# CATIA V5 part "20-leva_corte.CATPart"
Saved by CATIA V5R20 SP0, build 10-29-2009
Part number: 20-leva_corte
Revision: ANY
Definition: UNKNOWN
Nomenclature: 20-leva_corte
Source: Unknown
Bounding box of the stored display mesh (mm): x -12.5 to 12.5, y -12.31 to 12.31, z -7 to 10.6
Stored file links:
  C:\Users\Utente\Desktop\IO LAVORO\3D X SITO CF\CUMSA\3D files CX.013058\CX 013058\20-leva_corte.CATPart
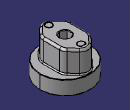
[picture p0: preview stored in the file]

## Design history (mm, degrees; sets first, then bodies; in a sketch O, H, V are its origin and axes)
Body1 "Redondeo5" (main body)
  Solid1: solid without history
